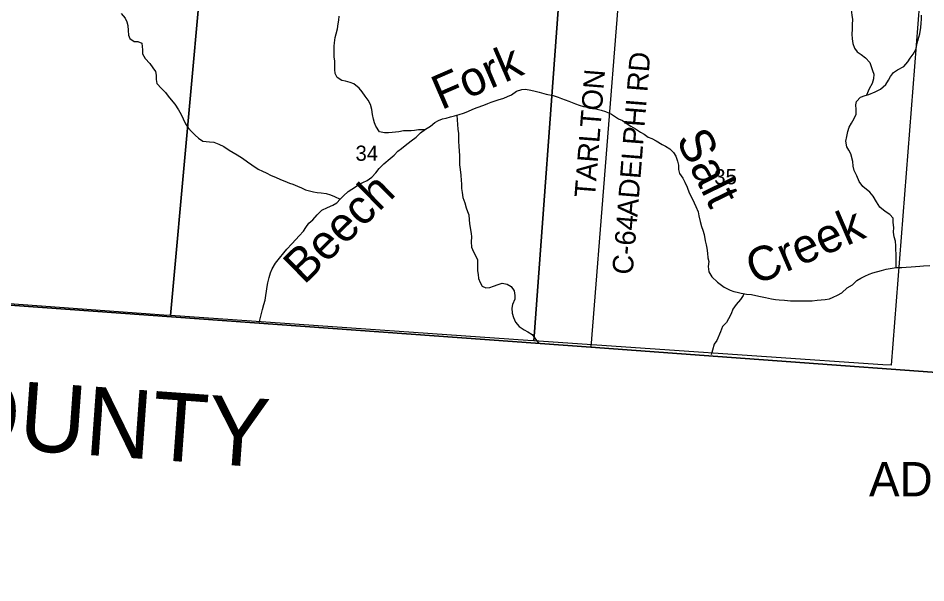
# Model space of a CAD drawing. Extents: x 1643459 to 2064572, y 425441 to 780708.
# Drawn here: x 1882681 to 1895923, y 531829 to 540058 of the extents above; entities that cross this region are included whole.
import ezdxf

# ---------------------------------------------------------------- set-up
doc = ezdxf.new("R2010")
doc.units = 0
for name, color, linetype in [('GM_P_County_Alignment', 7, 'Continuous'), ('GM_X_Adjacent_County', 7, 'Continuous'), ('GM_X_City_Street', 7, 'Continuous'), ('GM_X_Interchange_Ramps', 7, 'Continuous'), ('GM_X_Interstate_Route', 7, 'Continuous'), ('GM_X_Minor_Lake', 7, 'Continuous'), ('GM_X_Minor_River', 7, 'Continuous'), ('GM_X_Section_Text', 7, 'Continuous'), ('GM_X_State_Route', 7, 'Continuous'), ('GM_X_Township_Subdivision', 7, 'Continuous'), ('GM_X_Unincorporated_Text', 7, 'Continuous'), ('GM_X_US_Route', 7, 'Continuous')]:
    doc.layers.add(name, color=color, linetype=linetype)

msp = doc.modelspace()

# ---------------------------------------------------------------- linework, layer by layer
at = {"layer": 'GM_X_City_Street'}
msp.add_lwpolyline([(1897481, 534793), (1892687, 535143), (1891038, 535264), (1876915, 536283)], dxfattribs=at)
at = {"layer": 'GM_X_Interstate_Route'}
msp.add_lwpolyline([(1876915, 536283), (1891038, 535264), (1892687, 535143), (1897481, 534793)], dxfattribs=at)
at = {"layer": 'GM_X_Minor_Lake'}
for points in [[(1891039, 535264), (1891458, 540534)], [(1881236, 535971), (1891039, 535264), (1892687, 535143), (1897481, 534793)]]:
    msp.add_lwpolyline(points, dxfattribs=at)
at = {"layer": 'GM_X_Minor_River'}
msp.add_lwpolyline([(1876915, 536283), (1891038, 535264), (1892687, 535143), (1897481, 534793), (1897531, 534790), (1897918, 534771), (1897930, 535090), (1898290, 535082), (1898567, 535062), (1899290, 534983), (1900577, 534864), (1900566, 534649), (1900438, 532728), (1899791, 522947), (1899552, 519157)], dxfattribs=at)
at = {"layer": 'GM_X_State_Route'}
for points in [[(1885382, 540977), (1884902, 535726), (1884806, 535732), (1879705, 536104), (1880129, 541361)], [(1885382, 540977), (1890589, 540577), (1890205, 535356), (1890115, 535362), (1884902, 535726)], [(1890589, 540577), (1895832, 540288), (1895415, 535000), (1895294, 535008), (1890205, 535356)]]:
    msp.add_lwpolyline(points, close=True, dxfattribs=at)
at = {"layer": 'GM_X_Unincorporated_Text'}
for points in [[(1895490, 536427), (1895490, 536427), (1895491, 536575), (1895489, 536625), (1895487, 536683), (1895487, 536739), (1895481, 536807), (1895461, 536870), (1895449, 536942), (1895455, 537010), (1895448, 537082), (1895446, 537142), (1895398, 537195), (1895328, 537239), (1895254, 537303), (1895204, 537384), (1895154, 537462), (1895108, 537521), (1895004, 537605), (1894950, 537678), (1894917, 537760), (1894879, 537836), (1894861, 537901), (1894859, 537969), (1894831, 538081), (1894799, 538133), (1894771, 538184), (1894758, 538264), (1894772, 538336), (1894786, 538406), (1894804, 538470), (1894840, 538530), (1894878, 538598), (1894905, 538660), (1894907, 538726), (1894901, 538794), (1894913, 538844), (1894971, 538908), (1895039, 538930), (1895090, 538948), (1895184, 538985), (1895264, 539025), (1895338, 539093), (1895378, 539153), (1895409, 539209), (1895453, 539267), (1895509, 539306), (1895601, 539352), (1895661, 539424), (1895694, 539476), (1895740, 539536), (1895780, 539610), (1895790, 539670), (1895806, 539730), (1895823, 539782), (1895835, 539832), (1895851, 539922), (1895853, 539986), (1895859, 540046), (1895859, 540100)], [(1895490, 536427), (1895574, 536426), (1895638, 536430), (1895710, 536435), (1895773, 536439), (1895837, 536443), (1895887, 536449), (1895981, 536456)]]:
    msp.add_lwpolyline(points, dxfattribs=at)
at = {"layer": 'GM_X_US_Route'}
for points in [[(1894763, 540404), (1894814, 540276), (1894832, 540180), (1894844, 540103), (1894852, 540037), (1894848, 539967), (1894846, 539899), (1894843, 539827), (1894849, 539759), (1894857, 539688), (1894883, 539622), (1894919, 539568), (1894979, 539528), (1895043, 539481), (1895105, 539411), (1895127, 539352), (1895147, 539298), (1895164, 539244), (1895160, 539172), (1895142, 539104), (1895098, 539028), (1895058, 538937)], [(1884184, 540126), (1884244, 540057), (1884266, 540003), (1884282, 539951), (1884288, 539877), (1884290, 539810), (1884312, 539760), (1884376, 539716), (1884428, 539718), (1884488, 539693), (1884493, 539595), (1884493, 539539), (1884533, 539472), (1884601, 539396), (1884647, 539336), (1884687, 539283), (1884693, 539229), (1884697, 539165), (1884705, 539107), (1884772, 539034), (1884830, 538974), (1884870, 538920), (1884912, 538869), (1884966, 538803), (1885020, 538723), (1885060, 538654), (1885090, 538590), (1885124, 538520), (1885160, 538461), (1885208, 538405), (1885262, 538353), (1885313, 538310), (1885377, 538266), (1885474, 538257), (1885538, 538249), (1885608, 538223), (1885680, 538186), (1885758, 538136), (1885818, 538101), (1885874, 538067), (1885956, 538016), (1886028, 537966), (1886092, 537920), (1886184, 537859), (1886248, 537831), (1886298, 537806), (1886370, 537764), (1886436, 537740), (1886510, 537707), (1886574, 537685), (1886638, 537656), (1886690, 537638), (1886758, 537612), (1886816, 537587), (1886874, 537555), (1886990, 537526), (1887042, 537520), (1887102, 537512), (1887174, 537501), (1887238, 537483), (1887294, 537459), (1887377, 537420)], [(1888609, 538430), (1888522, 538429), (1888464, 538421), (1888414, 538417), (1888360, 538416), (1888304, 538414), (1888233, 538400), (1888137, 538391), (1888083, 538387), (1888025, 538385), (1887951, 538400), (1887901, 538482), (1887879, 538532), (1887865, 538584), (1887852, 538655), (1887842, 538727), (1887822, 538799), (1887786, 538863), (1887742, 538924), (1887702, 538984), (1887654, 539040), (1887576, 539099), (1887524, 539119), (1887458, 539142), (1887402, 539152), (1887334, 539194), (1887306, 539252), (1887300, 539311), (1887303, 539383), (1887301, 539435), (1887291, 539491), (1887291, 539571), (1887293, 539649), (1887297, 539701), (1887308, 539776), (1887320, 539832), (1887338, 539904), (1887350, 539974), (1887358, 540028), (1887366, 540086)], [(1886199, 535618), (1886231, 535754), (1886247, 535814), (1886267, 535886), (1886283, 535950), (1886293, 536019), (1886303, 536079), (1886316, 536147), (1886326, 536201), (1886342, 536281), (1886362, 536347), (1886386, 536407), (1886437, 536489), (1886493, 536563), (1886555, 536639), (1886603, 536694), (1886676, 536772), (1886734, 536832), (1886782, 536884), (1886846, 536954), (1886880, 537008), (1886923, 537072), (1886981, 537120), (1887045, 537193), (1887113, 537259), (1887194, 537297), (1887272, 537335), (1887330, 537368), (1887378, 537420), (1887428, 537470), (1887498, 537534), (1887605, 537600), (1887657, 537637), (1887711, 537665), (1887771, 537693), (1887839, 537741), (1887898, 537802), (1887950, 537866), (1888016, 537936), (1888106, 538012), (1888167, 538060), (1888221, 538118), (1888273, 538161), (1888325, 538203), (1888417, 538273), (1888486, 538325), (1888552, 538389), (1888626, 538442), (1888696, 538484), (1888760, 538536), (1888813, 538566), (1888871, 538589), (1888925, 538603), (1888989, 538621), (1889045, 538635), (1889113, 538654), (1889177, 538674), (1889243, 538698), (1889316, 538730), (1889380, 538757), (1889474, 538791), (1889534, 538817), (1889584, 538834), (1889686, 538868), (1889769, 538894), (1889821, 538915), (1889879, 538941), (1889951, 538993), (1890027, 539017), (1890083, 539022), (1890161, 539010), (1890223, 538996), (1890281, 538981), (1890384, 538949), (1890484, 538930), (1890558, 538906), (1890608, 538888), (1890716, 538847), (1890812, 538812), (1890868, 538792), (1890930, 538772), (1890990, 538763), (1891042, 538749), (1891110, 538739), (1891186, 538718), (1891250, 538696), (1891336, 538660), (1891438, 538589), (1891498, 538565), (1891564, 538516), (1891620, 538486), (1891686, 538445), (1891758, 538399), (1891812, 538369), (1891874, 538326), (1891926, 538304), (1891990, 538269), (1892076, 538219), (1892126, 538193), (1892190, 538152), (1892242, 538100)], [(1889081, 538645), (1889097, 538442), (1889103, 538378), (1889104, 538324), (1889104, 538260), (1889108, 538191), (1889114, 538121), (1889118, 538059), (1889118, 537997), (1889121, 537921), (1889129, 537855), (1889139, 537772), (1889143, 537694), (1889147, 537642), (1889151, 537578), (1889159, 537516), (1889170, 537446), (1889196, 537365), (1889218, 537293), (1889238, 537243), (1889254, 537193), (1889262, 537120), (1889266, 537066), (1889276, 537002), (1889291, 536922), (1889295, 536870), (1889291, 536800), (1889293, 536723), (1889325, 536655), (1889351, 536601), (1889383, 536535), (1889384, 536482), (1889382, 536432), (1889384, 536374), (1889390, 536324), (1889398, 536264), (1889422, 536206), (1889450, 536153), (1889504, 536127), (1889562, 536131), (1889614, 536153), (1889684, 536178), (1889740, 536194), (1889816, 536184), (1889872, 536147), (1889916, 536087), (1889928, 536015), (1889928, 535961), (1889894, 535887), (1889882, 535831), (1889889, 535760), (1889907, 535696), (1889937, 535628), (1889989, 535564), (1890065, 535515), (1890119, 535489), (1890181, 535448), (1890274, 535322)], [(1892242, 538100), (1892276, 538048), (1892302, 537973), (1892316, 537915), (1892315, 537851), (1892331, 537793), (1892379, 537728), (1892409, 537670), (1892441, 537594), (1892471, 537512), (1892513, 537429), (1892541, 537369), (1892566, 537315), (1892602, 537236), (1892612, 537176), (1892630, 537094), (1892648, 537024), (1892672, 536971), (1892690, 536907), (1892705, 536811), (1892719, 536757), (1892727, 536707), (1892737, 536636), (1892745, 536566), (1892755, 536510), (1892747, 536438), (1892756, 536360), (1892800, 536287), (1892882, 536213), (1892980, 536136), (1893068, 536092), (1893120, 536077), (1893170, 536063), (1893230, 536051), (1893306, 536038), (1893379, 536030), (1893485, 536009), (1893583, 535989), (1893673, 535966), (1893731, 535958), (1893785, 535954), (1893863, 535947), (1893947, 535941), (1894039, 535938), (1894209, 535938), (1894267, 535939), (1894338, 535947), (1894398, 535955), (1894452, 535959), (1894518, 535968), (1894570, 535990), (1894634, 536020), (1894698, 536054), (1894777, 536127), (1894851, 536173), (1894915, 536235), (1894977, 536269), (1895035, 536300), (1895095, 536326), (1895152, 536346), (1895278, 536381), (1895344, 536401), (1895490, 536427)], [(1895488, 536499), (1895488, 536498)], [(1893274, 536044), (1893258, 536016), (1893218, 535959), (1893158, 535887), (1893106, 535819), (1893081, 535751), (1893043, 535675), (1893013, 535621), (1892959, 535565), (1892929, 535489), (1892876, 535359), (1892834, 535307), (1892810, 535221), (1892790, 535153)]]:
    msp.add_lwpolyline(points, dxfattribs=at)

# ---------------------------------------------------------------- texts
at = {"layer": 'GM_P_County_Alignment'}
msp.add_text('ADELPHI', height=500, rotation=0, dxfattribs=at).set_placement((1895094, 533090))
at = {"layer": 'GM_X_Adjacent_County'}
for s, p in [('34', (1887603, 537980)), ('35', (1892837, 537637))]:
    msp.add_text(s, height=221, rotation=0, dxfattribs=at).set_placement(p)
at = {"layer": 'GM_X_Interchange_Ramps'}
for s, rotation, p in [('Fork', 23.3764, (1888856, 538716)), ('Salt', 296.3741, (1892272, 538294)), ('Beech', 44.377, (1886854, 536164)), ('Creek', 23.3765, (1893435, 536161))]:
    msp.add_text(s, height=500, rotation=rotation, dxfattribs=at).set_placement(p)
at = {"layer": 'GM_X_Section_Text'}
for s, rotation, p in [('ADELPHI RD', 85.4588, (1891715, 537155)), ('TARLTON', 85.4316, (1891095, 537435)), ('C-64', 85.1793, (1891644, 536312))]:
    msp.add_text(s, height=300, rotation=rotation, dxfattribs=at).set_placement(p)
at = {"layer": 'GM_X_Township_Subdivision'}
msp.add_text('ROSS COUNTY', height=1000, rotation=355.8825, dxfattribs=at).set_placement((1876522, 534210))

doc.saveas('drawing.dxf')
